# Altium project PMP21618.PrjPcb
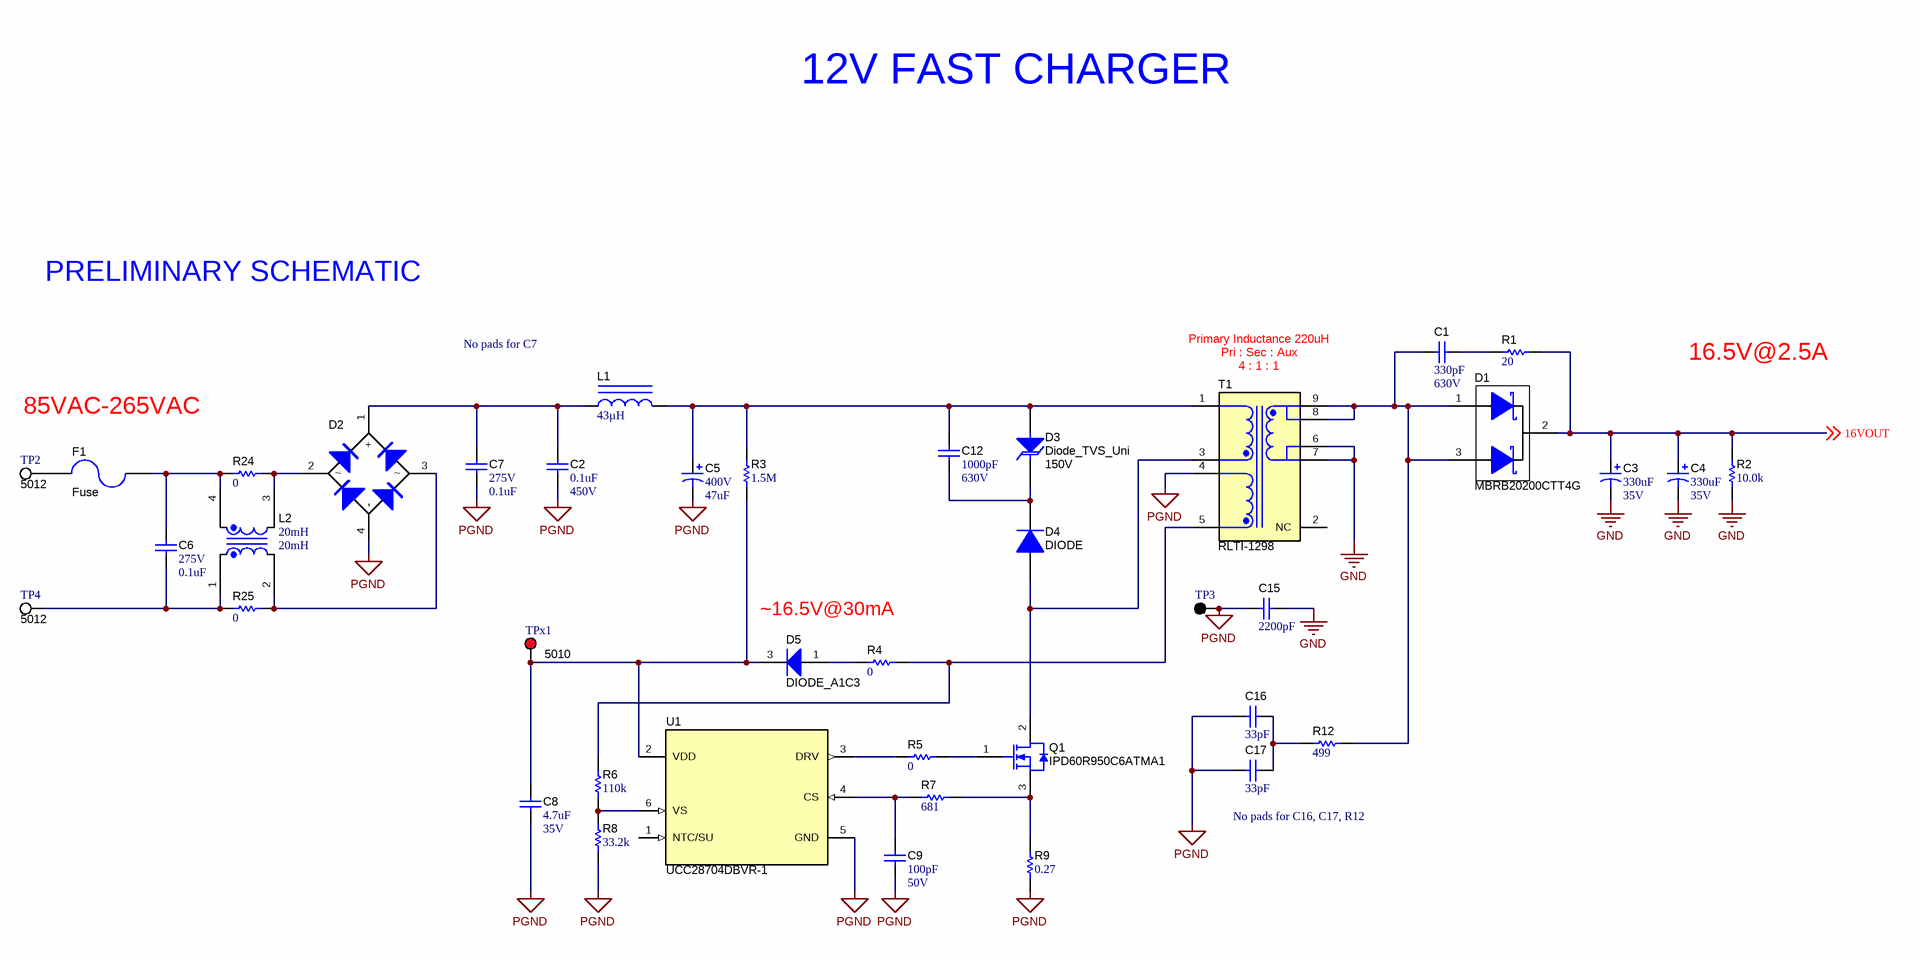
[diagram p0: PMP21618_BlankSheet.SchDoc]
TID: N/A; TechSupport: http://www.ti.com/support; SCH_Rev: A; PRJ_Number: PMP21618; PRJ_Engineer: S. Abedin; PRJ_Customer: Public Release; PCB_Rev: A; PCB_Layout: S. Abedin; CopyrightYear: 2017
2 sheets, 79 parts. Net scope: global (net labels, ports and power ports of the same name join across sheets).
Board file: PMP21618_PCB.PcbDoc
Sheets:
  PMP21618_BlankSheet.SchDoc
  BQ24725Z.SchDoc

## Sheet PMP21618_BlankSheet.SchDoc
size 431 x 279 mm; Date: Not shown in title block; ApprovedBy: Not shown in title block; CheckedBy: Not shown in title block; Author: Not shown in title block; CompanyName: Not shown in title block; Engineer: Not shown in title block; Organization: Not shown in title block; Address1: Not shown in title block; Address2: Not shown in title block; Address3: Not shown in title block; Address4: Not shown in title block; DocumentNumber: 1; Revision: Use project parameter SCH_Rev; SheetNumber: 1; SheetTotal: 2; PageSetup: Record=PageOptions¦CenterHorizontal=True¦CenterVertical=True¦PrintScale=1.00¦XCorrection=1.00¦YCorrection=1.00¦PrintKind=0¦BorderSize=5000000¦LeftOffset=0¦BottomOffset=0¦Orientation=2¦PaperLength=1000¦PaperWidth=1000¦Scale=100¦PaperSource=15¦PrintQuality=600¦MediaType=1¦DitherType=10¦PaperKind=Letter¦PrintScaleMode=1

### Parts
C1  ValueDisplayed: 330pF  VDC_V: 630V  [1206]  (hidden comment: Capacitor)
C2  ValueDisplayed: 0.1uF  VDC_V: 450V  [1206_190]  (hidden comment: Capacitor)
C3  ValueDisplayed: 330uF  VDC_V: 35V  [Chemi-Con_1000x1600]  (hidden comment: Cap_Polarized)
C4  ValueDisplayed: 330uF  VDC_V: 35V  [Chemi-Con_1000x1600]  (hidden comment: Cap_Polarized)
C5  VDC_V: 400V  ValueDisplayed: 47uF  [EE_1800x2000_HorizontalUp]  (hidden comment: EEU-EE2G470S)
C6  VDC_V: 275V  ValueDisplayed: 0.1uF  [WCAP-FTX2_1800x600x1200]  (hidden comment: 890324025017)
C7  VDC_V: 275V  ValueDisplayed: 0.1uF  [WCAP-FTX2_1800x600x1200]  (hidden comment: 890324025017)
C8  ValueDisplayed: 4.7uF  VDC_V: 35V  [0805_HV]  (hidden comment: Capacitor)
C9  ValueDisplayed: 100pF  VDC_V: 50V  [0402S]  (hidden comment: Capacitor)
C12  ValueDisplayed: 1000pF  VDC_V: 630V  [1206]  (hidden comment: Capacitor)
C15  ValueDisplayed: 2200pF  [KY_800x500x1100]  (hidden comment: DE2E3KY222MA2BM01F)
C16  ValueDisplayed: 33pF  [KY_800x500x1100_7_5]  (hidden comment: DE21XKY330JN3AM02F)
C17  ValueDisplayed: 33pF  [KY_800x500x1100_7_5]  (hidden comment: DE21XKY330JN3AM02F)
D1  MBRB20200CTT4G  [DDPAK]
D2  DIODE_BRIDGE_Pos1_Neg4_AC23  [Z4-D]  (value not drawn)
D3  Diode_TVS_Uni  value 150V  [SMC]
D4  DIODE  [SMA]
D5  DIODE_A1C3  [SOT-23]
F1  Fuse  [FUSE_372]
L1  ValueDisplayed: 43µH  [WE-FI_1300x650]  (hidden comment: 7447034)
L2  value 20mH  ValueDisplayed: 20mH  [IND_WE-CMB-S]  (hidden comment: 744822120)
Q1  IPD60R950C6ATMA1  [DPAK]
R1  ValueDisplayed: 20  [1206]  (hidden comment: Resistor)
R2  ValueDisplayed: 10.0k  [0402S]  (hidden comment: Resistor)
R3  ValueDisplayed: 1.5M  [0805_HV]  (hidden comment: Resistor)
R4  ValueDisplayed: 0  [0603]  (hidden comment: Resistor)
R5  ValueDisplayed: 0  [0402S]  (hidden comment: Resistor)
R6  ValueDisplayed: 110k  [0402S]  (hidden comment: Resistor)
R7  ValueDisplayed: 681  [0402S]  (hidden comment: Resistor)
R8  ValueDisplayed: 33.2k  [0402S]  (hidden comment: Resistor)
R9  ValueDisplayed: 0.27  [1210L]  (hidden comment: Resistor)
R12  ValueDisplayed: 499  [0805_HV]  (hidden comment: RG2012P-4990-B-T5)
R24  ValueDisplayed: 0  [2010]  (hidden comment: Resistor)
R25  ValueDisplayed: 0  [2010]  (hidden comment: Resistor)
T1  RLTI-1298  [Renco_RLTI-1298]
TP2  5012  [Keystone5012]
TP3  5011  [Keystone5011]  (value not drawn)
TP4  5012  [Keystone5012]
TPx1  5010  [Keystone5010]
U1  UCC28704DBVR-1  [DBV0006A_N]

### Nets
GND: C3.2(-) C4.2(-) C15.1 R2.1 T1.6 T1.7
PGND: C2.2 C5.2(-) C7.2 C8.2 C9.2 C15.2 C16.2 C17.2 D2.4(-) R8.1 R9.1 T1.4 TP3.1 U1.5(GND)
16VOUT: C3.1(+) C4.1(+) D1.2(K) R1.2 R2.2 ; off-sheet 16VOUT
NetC1_1: C1.1 R1.1
NetC1_2: C1.2 D1.1(A) D1.3(A) R12.2 T1.8 T1.9
NetC2_1: C2.1 C7.1 D2.1(+) L1.1
NetC5_1: C5.1(+) C12.1 D3.2(A) L1.2 R3.2 T1.1
NetC6_1: C6.1 F1.1 L2.4 R24.1
NetC6_2: C6.2 L2.1 R25.1 TP4.1
NetC8_1: C8.1 D5.3(K) R3.1 TPx1.1 U1.2(VDD)
NetC9_1: C9.1 R7.1 U1.4(CS)
NetC12_2: C12.2 D3.1(K) D4.1(K)
NetC16_1: C16.1 C17.1 R12.1
NetD2_2: D2.2 L2.3 R24.2
NetD2_3: D2.3 L2.2 R25.2
NetD4_2: D4.2(A) Q1.2(D) T1.3
NetD5_1: D5.1(A) R4.1
NetF1_2: F1.2 TP2.1
NetQ1_1: Q1.1(G) R5.2
NetQ1_3: Q1.3(S) R7.2 R9.2
NetR4_2: R4.2 R6.2 T1.5
NetR5_1: R5.1 U1.3(DRV)
NetR6_1: R6.1 R8.2 U1.6(VS)

Not connected (* = marked no-connect by the designer): T1 2(NC); U1 1(NTC/SU)

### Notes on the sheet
- 12V FAST CHARGER
- PRELIMINARY SCHEMATIC
- No pads for C7
- (near T1) Pri : Sec : Aux
- (near T1) 4 : 1 : 1
- Primary Inductance 220uH
- 16.5V@2.5A
- 85VAC-265VAC
- 6.5V@30mA
- (near C17) No pads for C16, C17, R12

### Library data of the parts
C1 = CMP-0008887-2: CAP, CERM, 330 pF, 630 V, +/- 5%, C0G/NP0, 1206; PartNumber: GRM31A5C2J331JW01D; Manufacturer: MuRata; Polarized: N; Value: 330pF; U/M: EA; Value1: Unknown; TaMin_C: -55°C; TaMax_C: 125°C; SizeArea_mm2: 5.12; SizeAreaWB_mm2: 10.92; SizeX_mm: 3.2; SizeY_mm: 1.6; SizeZ_mm: 1.35; AEC Category: Q200
C2 = CMP-0008727-2: CAP, CERM, 0.1 uF, 450 V, +/- 10%, X7T, 1206_190; PartNumber: C3216X7T2W104K160AA; Manufacturer: TDK; Polarized: N; Value: 0.1uF; U/M: EA; Cap_F: 100nF; Value1: Unknown; TaMin_C: -55°C; TaMax_C: 125°C; Cap_Case: 1206; SizeArea_mm2: 5.12; SizeAreaWB_mm2: 10.92; SizeX_mm: 3.2; SizeY_mm: 1.6; SizeZ_mm: 1.9; AEC Category: Q200
C3 C4 = CMP-0010424-2: CAP, AL, 330 uF, 35 V, +/- 20%, TH; PartNumber: EKZE350ELL331MJ16S; Manufacturer: Chemi-Con; Polarized: Y; CompType: Capacitor; Value: 330uF; U/M: EA; Cap_F: 330µF; Value1: Unknown; IRMS_A: 1.43A; TaMin_C: -40°C; TaMax_C: 105°C; Cap_Case: 10x16; SizeAreaWB_mm2: 144; SizeArea_mm2: 100; SizeX_mm: 10; SizeZ_mm: 17.5; AEC Category: Q200; AEC Qualified: N
C5 = CMP-0010026-3: CAP, AL, 47 uF, 400 V, +/- 20%, TH; Manufacturer: Panasonic; TaMin_C: -25°C; Polarized: Y; SizeAreaWB_mm2: 400; Value1: Unknown; U/M: EA; Value: 47uF; TaMax_C: 105°C; SizeZ_mm: 22; SizeX_mm: 18; Cap_Case: 18x20; SizeArea_mm2: 324; CompType: Capacitor; AEC Qualified: N; Cap_F: 47µF; IRMS_A: 1.18A; AEC Category: Q200
C6 C7 = CMP-0012314-3: CAP, Film, 0.1 uF, 275 V, +/- 10%, TH; Manufacturer: Wurth Elektronik; TaMin_C: -40°C; Polarized: N; Value1: Unknown; Value: 0.1uF; TaMax_C: 105°C; Cap_Case: 18x6x12mm; Cap_F: 100nF; AEC Category: Q200
C8 = CMP-0007885-2: CAP, CERM, 4.7 uF, 35 V, +/- 10%, X7R, 0805; PartNumber: C2012X7R1V475K125AC; Manufacturer: TDK; Polarized: N; Value: 4.7uF; U/M: EA; Cap_F: 4.7µF; ESR_ohm: 2.346m; Value1: 0.002346 ohm; IRMS_A: 4.26021A; TaMin_C: -55°C; TaMax_C: 125°C; Cap_Case: 0805; SizeArea_mm2: 2.5; SizeAreaWB_mm2: 6.75; SizeX_mm: 2; SizeY_mm: 1.25; SizeZ_mm: 1.45; AEC Category: Q200
C9 = CMP-0006410-2: CAP, CERM, 100 pF, 50 V, +/- 5%, C0G/NP0, 0402; PartNumber: GRM1555C1H101JA01D; Manufacturer: MuRata; Polarized: N; Value: 100pF; U/M: EA; Value1: Unknown; TaMin_C: -55°C; TaMax_C: 125°C; Cap_Case: 0402; SizeArea_mm2: 0.5; SizeAreaWB_mm2: 3; SizeX_mm: 1; SizeZ_mm: 0.6; AEC Category: Q200
C12 = CMP-0008909-2: CAP, CERM, 1000 pF, 630 V, +/- 10%, X7R, 1206; PartNumber: GRM31BR72J102KW01L; Manufacturer: MuRata; Polarized: N; Value: 1000pF; U/M: EA; Cap_F: 1nF; Value1: Unknown; TaMin_C: -55°C; TaMax_C: 125°C; SizeArea_mm2: 5.12; SizeAreaWB_mm2: 10.92; SizeX_mm: 3.2; SizeY_mm: 1.6; SizeZ_mm: 1.35; AEC Category: Q200
C15 = CMP-0067532-1: CAP, CERM, 2200 pF, X1 250 VAC/Y2 250 VAC, +/- 20%, E, 8x5mm; Manufacturer: MuRata; TaMin_C: -40°C; AC_Safety: X1Y2; Polarized: N; SizeAreaWB_mm2: 70.0; Value1: Unknown; U/M: EA; Value: 2200pF; TaMax_C: 125°C; VAC_X: 250; SizeZ_mm: 11.0; SizeX_mm: 8.0; SizeY_mm: 5.0; Cap_Case: 8x5x11mm; Value2: V; SizeArea_mm2: 40.0; Cap_F: 2.2nF; AEC Category: Q200
C16 C17 = CMP-0081721-1: CAP, CERM, 33 pF, X1 250 VAC/Y2 250 VAC, +/- 5%, SL, 8x5mm; Manufacturer: MuRata; TaMin_C: -40°C; Polarized: N; AC_Safety: X1Y2; SizeAreaWB_mm2: 71.05; U/M: EA; Value: 33pF; TaMax_C: 125°C; VAC_Y: 250V; SizeZ_mm: 11; SizeX_mm: 8.15; SizeY_mm: 5; Cap_Case: 8x5x11mm; SizeArea_mm2: 40.75; AEC Category: Q200
D1 = CMP-0028500-3: Diode, Schottky, 200 V, 20 A, DDPAK; Manufacturer: ON Semiconductor; Io_A: 20A; Green_Lifecycle: Not Set; SizeAreaWB_mm2: 209.6992; Vr_V: 200V; Green_REACh: Incomplete; TJmax_C: 150°C; Value: 200V; SizeZ_mm: 4.445; SizeX_mm: 15.245; SizeY_mm: 10.16; Vf_V: 1V; SizeArea_mm2: 154.8892; AEC Category: Q101; RJC_CperW: 2
D2 = CMP-0029244-3: Diode, P-N-Bridge, 600 V, 4 A, Z4-D; PartNumber: Z4DGP406L-HF; Manufacturer: Comchip Technology; Vf_V: 9.5dV; Value: 600V; Value1: 4A; Value2: 0.95V; TJmax_C: 175°C; AEC Category: Q101; AEC Qualified: N; Green_Lifecycle: Not Set; Green_REACh: Incomplete; SizeArea_mm2: 85.05; SizeAreaWB_mm2: 126.25; SizeX_mm: 10.5; SizeY_mm: 8.1; SizeZ_mm: 1.55
D3 = CMP-0005708-2: Diode, TVS, Uni, 150 V, 243 Vc, SMC; PartNumber: SMCJ150A-TP; Manufacturer: Micro Commercial Components; U/M: EA; Value1: W; SizeAreaWB_mm2: 83.2686; SizeArea_mm2: 50.5686; SizeX_mm: 8.13; SizeY_mm: 6.22; SizeZ_mm: 2.6; AEC Category: Q101; AEC Qualified: N
D4 = CMP-0029033-2: Diode, Ultrafast, 600 V, 1 A, AEC-Q101, SMA; PartNumber: MURA160T3G; Manufacturer: ON Semiconductor; Vf_V: 1.05V; Value: 600V; Value1: 1A; TJmax_C: 175°C; SizeAreaWB_mm2: 37.3428; SizeArea_mm2: 16.3228; SizeX_mm: 5.59; SizeY_mm: 2.92; SizeZ_mm: 2.87; AEC Category: Q101; AEC Qualified: Y; Green_Lifecycle: Active; Green_REACh: Passed
D5 = CMP-0076901-2: Diode, Switching, 200 V, 0.2 A, SOT-23; PartNumber: BAS21-7-F; Manufacturer: Diodes Inc.; Vf_V: 1.25V; Value: 200V; Value1: 0.2A; Io_A: 2dA; TJmax_C: 150°C; SizeAreaWB_mm2: 14.0; SizeArea_mm2: 7.5; SizeX_mm: 2.5; SizeY_mm: 3.0; SizeZ_mm: 1.1; AEC Category: Q101; Green_Lifecycle: Active; Green_REACh: Passed
F1 = CMP-0003553-2: Fuse, 1.25 A, 250VAC/VDC, TH; PartNumber: 37211250001; Manufacturer: Littelfuse; VDC_V: 250V; Irating_A: 1.25A
L1 = CMP-0750103-1: Inductor, Toroid, Ferrite, 43 µH, 1 A, 0.06 ohm, TH; Manufacturer: Wurth Elektronik; Irms: 2.6A @ 40C rise; SizeArea_mm2: 84.5; SizeZ_mm: 13; SizeX_mm: 6.5; DCR_ohm: 0.06; AEC Qualified: N; Imax_A: 1A; SizeAreaWB_mm2: 127.5; AEC Category: Q200; Value: 43uH
L2 = CMP-0084404-1: Coupled inductor, 20 mH, 0.54 ohm, TH; Manufacturer: Wurth Elektronik; AEC Category: Q200; DCR_ohm: 5.4d; AEC Qualified: N
Q1 = CMP-0067579-2: MOSFET, N-CH, 600 V, 4.4 A, DPAK; Alternate Manufacturer: None; Manufacturer: Infineon Technologies; QgTyp_nC: 13.0; SizeAreaWB_mm2: 101.7114; Vgs_V: 20V; Value1: ? ohm; VdsMax_V: 600V; Value: 600V; IdsMax_A: 4.4A; SizeZ_mm: 2.29; SizeX_mm: 9.91; SizeY_mm: 6.54; Value2: 13 nC; SizeArea_mm2: 64.8114; ChType: N; AEC Category: Q101; ChMode: Enhancement
R1 = CMP-0018627-3: RES, 20, 5%, 0.25 W, AEC-Q200 Grade 0, 1206; PartNumber: CRCW120620R0JNEA; Manufacturer: Vishay-Dale; Value: 20; Value_Code: 20R0; Power_W: 250mW; Value2: 0.25W; VDC_V: 200V; TempCo: 200 ppm/C; SizeArea_mm2: 5.12; SizeX_mm: 3.2; SizeY_mm: 1.6; SizeZ_mm: 1.35; EIA_Code: E24; AEC Category: Q200; AEC Qualified: Y; AEC Grade: 0
R2 = CMP-0025958-3: RES, 10.0 k, 1%, 0.063 W, AEC-Q200 Grade 0, 0402; PartNumber: CRCW040210K0FKED; Manufacturer: Vishay-Dale; Value: 10.0k; Res_ohm: 10k; Value_Code: 10k0; Power_W: 63mW; Value2: 0.063W; VDC_V: 50V; TempCo: 100 ppm/C; SizeArea_mm2: 0.5; SizeX_mm: 1; SizeZ_mm: 0.6; EIA_Code: E96; AEC Category: Q200; AEC Qualified: Y; AEC Grade: 0
R3 = CMP-0020484-3: RES, 1.5 M, 5%, 0.125 W, AEC-Q200 Grade 0, 0805; PartNumber: CRCW08051M50JNEA; Manufacturer: Vishay-Dale; Value: 1.5Meg; Value_Code: 1M50; Power_W: 125mW; Value2: 0.125W; VDC_V: 150V; TempCo: 200 ppm/C; SizeArea_mm2: 2.5; SizeX_mm: 2; SizeY_mm: 1.25; SizeZ_mm: 1.45; EIA_Code: E24; AEC Category: Q200; AEC Qualified: Y; AEC Grade: 0
R4 = CMP-0025697-4: RES, 0, 5%, 0.1 W, AEC-Q200 Grade 0, 0603; PartNumber: CRCW06030000Z0EA; Manufacturer: Vishay-Dale; Value: 0; Value_Code: 0000; Power_W: 100mW; Value2: 0.1W; VDC_V: 75V; TempCo: 200 ppm/C; SizeArea_mm2: 1.28; SizeX_mm: 1.6; SizeY_mm: 0.8; SizeZ_mm: 1; EIA_Code: E24; AEC Category: Q200; AEC Qualified: Y
R5 = CMP-0026822-3: RES, 0, 5%, 0.063 W, AEC-Q200 Grade 0, 0402; PartNumber: CRCW04020000Z0ED; Manufacturer: Vishay-Dale; Value: 0; Value_Code: 0000; Power_W: 63mW; Value2: 0.063W; VDC_V: 50V; TempCo: 200 ppm/C; SizeArea_mm2: 0.5; SizeX_mm: 1; SizeZ_mm: 0.6; EIA_Code: E24; AEC Category: Q200; AEC Qualified: Y
R6 = CMP-0026828-2: RES, 110 k, 5%, 0.063 W, AEC-Q200 Grade 0, 0402; PartNumber: CRCW0402110KJNED; Manufacturer: Vishay-Dale; Value: 110k; Power_W: 63mW; Value2: 0.063W; VDC_V: 50V; TempCo: 200 ppm/C; SizeArea_mm2: 0.5; SizeX_mm: 1; SizeZ_mm: 0.6; EIA_Code: E24; AEC Category: Q200; AEC Qualified: Y; AEC Grade: 0
R7 = CMP-0026505-2: RES, 681, 1%, 0.063 W, AEC-Q200 Grade 0, 0402; PartNumber: CRCW0402681RFKED; Manufacturer: Vishay-Dale; Value: 681; Value_Code: 681R; Power_W: 63mW; Value2: 0.063W; VDC_V: 50V; TempCo: 100 ppm/C; SizeArea_mm2: 0.5; SizeX_mm: 1; SizeZ_mm: 0.6; EIA_Code: E96; AEC Category: Q200; AEC Qualified: Y; AEC Grade: 0
R8 = CMP-0026298-2: RES, 33.2 k, 1%, 0.063 W, AEC-Q200 Grade 0, 0402; PartNumber: CRCW040233K2FKED; Manufacturer: Vishay-Dale; Value: 33.2k; Value_Code: 33k2; Power_W: 63mW; Value2: 0.063W; VDC_V: 50V; TempCo: 100 ppm/C; SizeArea_mm2: 0.5; SizeX_mm: 1; SizeZ_mm: 0.6; EIA_Code: E96; AEC Category: Q200; AEC Qualified: Y; AEC Grade: 0
R9 = CMP-0015177-2: RES, 0.27, 1%, 0.5 W, 1210; PartNumber: MCR25JZHFLR270; Manufacturer: Rohm; Value: 0.27; Res_ohm: 2.7d; Value_Code: R270; Power_W: 500mW; Value2: 0.5W; VDC_V: 0V; TempCo: 200 ppm/C; SizeArea_mm2: 8; SizeAreaWB_mm2: 14.7; SizeX_mm: 3.2; SizeY_mm: 2.5; SizeZ_mm: 1.35; EIA_Code: E96; U/M: EA; AEC Category: Q200
R12 = CMP-0019000-2: RES, 499, 0.1%, 0.125 W, 0805; Manufacturer: Susumu Co Ltd; Power_W: 125mW; TempCo: 25 ppm/C; Value_Code: 499R; U/M: EA; Value: 499; EIA_Code: E192; SizeX_mm: 2; SizeY_mm: 1.25; SizeZ_mm: 1.45; Value2: 0.125W; SizeArea_mm2: 2.5; VDC_V: 100V; AEC Category: Q200
R24 R25 = CMP-0016044-3: RES, 0, 5%, 0.75 W, AEC-Q200 Grade 0, 2010; PartNumber: CRCW20100000Z0EF; Manufacturer: Vishay-Dale; Value: 0; Value_Code: 0000; Power_W: 750mW; Value2: 0.75W; TempCo: ppm/C; SizeArea_mm2: 12.5; SizeX_mm: 5; SizeY_mm: 2.5; SizeZ_mm: 1.66; EIA_Code: E24; AEC Category: Q200; AEC Qualified: Y
T1 = CMP-0084219-2: Transformer, 220 uH, TH; Manufacturer: Renco Electronics; SizeAreaWB_mm2: 1219.9488; SizeArea_mm2: 1083.8688; AEC Qualified: N; Ns2toNp: 0.25; Lp: 220; AEC Category: Q200; Value: 220uH; SizeZ_mm: 19.05; Ind_H: 220µH; SizeY_mm: 30.48; LeakageInd_H: 7µH; Rsec2_ohm: 0.012; Rsec1_ohm: 0.04; DCR_ohm: 0.1; SizeX_mm: 35.56
TP2 TP4 = CMP-0055149-1: Test Point, Multipurpose, White, TH; Manufacturer: Keystone; ContactFinish: Silver; Green_Lifecycle: Active; Green_REACh: Passed; CNHeader: FALSE; CT: TRUE
TP3 = CMP-0055148-1: Test Point, Multipurpose, Black, TH; Manufacturer: Keystone; ContactFinish: Silver; Green_Lifecycle: Active; Green_REACh: Passed; CNHeader: FALSE; CT: TRUE
TPx1 = CMP-0055147-1: Test Point, Multipurpose, Red, TH; Manufacturer: Keystone; ContactFinish: Silver; Green_Lifecycle: Active; Green_REACh: Passed; CNHeader: FALSE; CT: TRUE
U1 = CMP-0074087-1: Off-Line Constant-Voltage Constant-Current Flyback Controller With Primary-Side Regulation (PSR), DBV0006A (SOT-23-6); Alternate PartNumber: UCC28704DBVT-1; Alternate Manufacturer: Texas Instruments; Green_Lifecycle: Active; SizeAreaWB_mm2: 14.82; Green_REACh: Passed; U/M: EA; SizeZ_mm: 1.45; SizeX_mm: 2.8; SizeY_mm: 2.9; SizeArea_mm2: 8.12; CompType: IC

## Sheet BQ24725Z.SchDoc
size 431 x 279 mm; Date: Not shown in title block; ApprovedBy: Not shown in title block; CheckedBy: Not shown in title block; Author: Not shown in title block; CompanyName: Not shown in title block; Engineer: Not shown in title block; Organization: Not shown in title block; Address1: Not shown in title block; Address2: Not shown in title block; Address3: Not shown in title block; Address4: Not shown in title block; DocumentNumber: 2; Revision: Use project parameter SCH_Rev; SheetNumber: 2; SheetTotal: 2; PageSetup: Record=PageOptions¦CenterHorizontal=True¦CenterVertical=True¦PrintScale=1.00¦XCorrection=1.00¦YCorrection=1.00¦PrintKind=0¦BorderSize=5000000¦LeftOffset=0¦BottomOffset=0¦Orientation=2¦PaperLength=1000¦PaperWidth=1000¦Scale=100¦PaperSource=15¦PrintQuality=600¦MediaType=1¦DitherType=10¦PaperKind=Letter¦PrintScaleMode=1
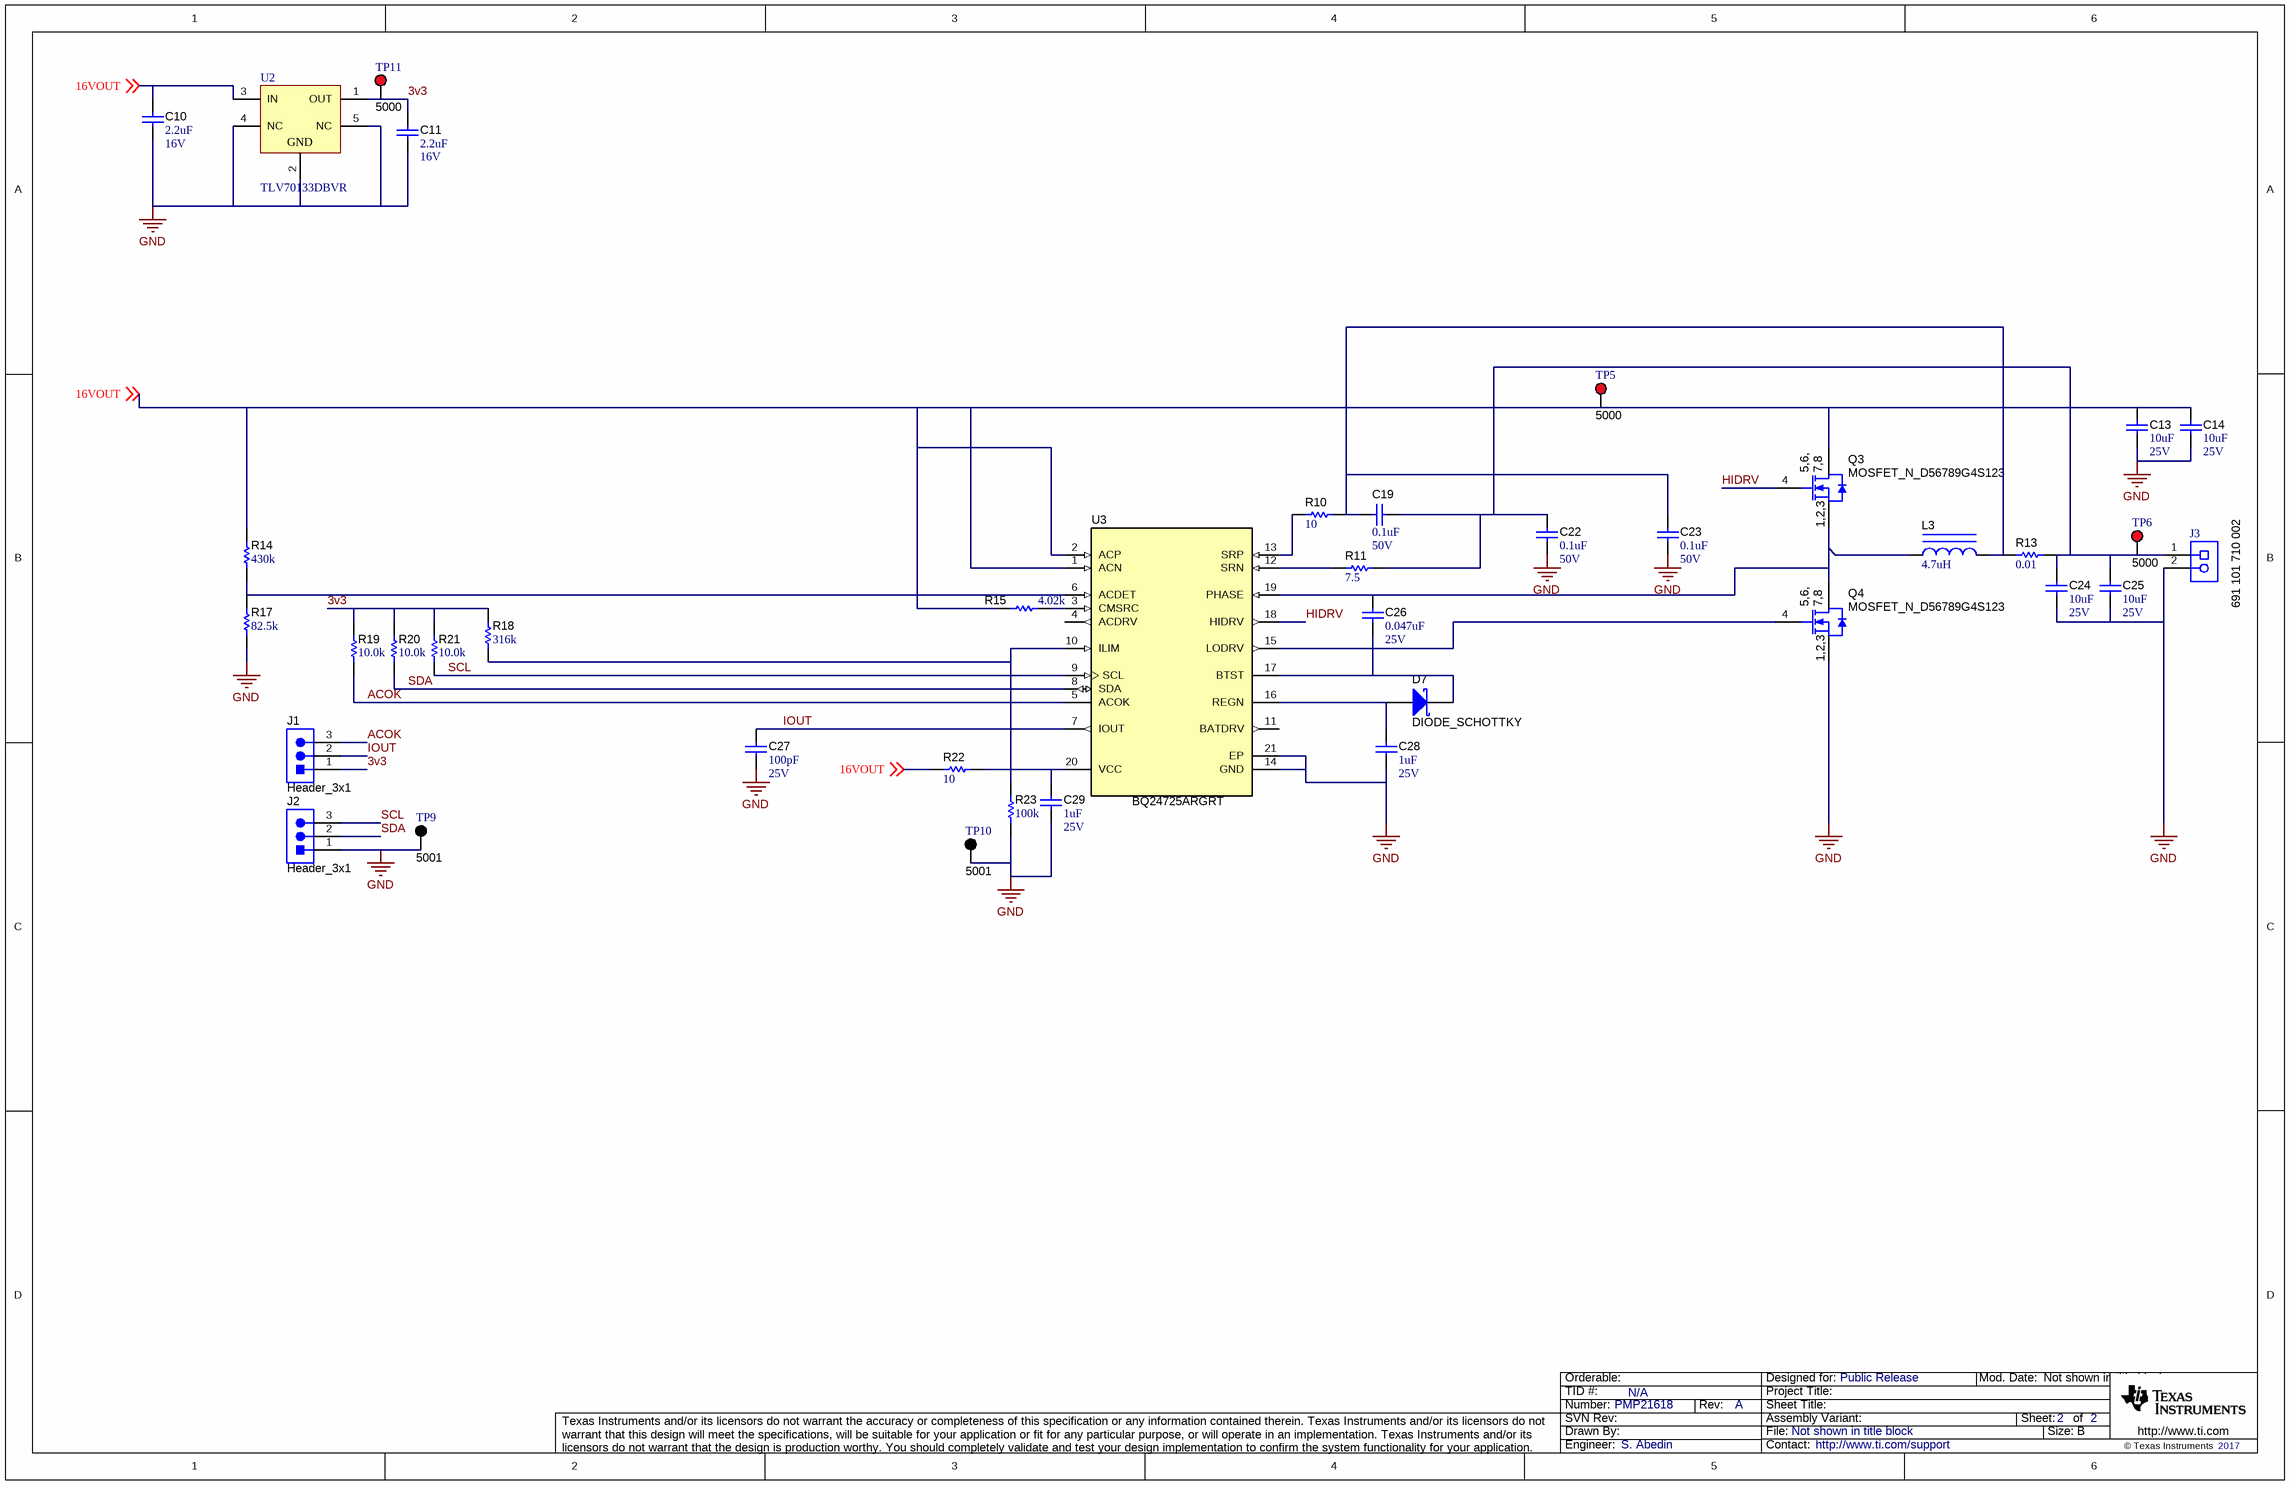
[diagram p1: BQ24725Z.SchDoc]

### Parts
C10  ValueDisplayed: 2.2uF  VDC_V: 16V  [0402S]  (hidden comment: Capacitor)
C11  ValueDisplayed: 2.2uF  VDC_V: 16V  [0402S]  (hidden comment: Capacitor)
C13  ValueDisplayed: 10uF  VDC_V: 25V  [0805_HV]  (hidden comment: Capacitor)
C14  ValueDisplayed: 10uF  VDC_V: 25V  [0805_HV]  (hidden comment: Capacitor)
C19  ValueDisplayed: 0.1uF  VDC_V: 50V  [0402S]  (hidden comment: Capacitor)
C22  ValueDisplayed: 0.1uF  VDC_V: 50V  [0402S]  (hidden comment: Capacitor)
C23  ValueDisplayed: 0.1uF  VDC_V: 50V  [0402S]  (hidden comment: Capacitor)
C24  ValueDisplayed: 10uF  VDC_V: 25V  [0805_HV]  (hidden comment: Capacitor)
C25  ValueDisplayed: 10uF  VDC_V: 25V  [0805_HV]  (hidden comment: Capacitor)
C26  ValueDisplayed: 0.047uF  VDC_V: 25V  [0402S]  (hidden comment: Capacitor)
C27  ValueDisplayed: 100pF  VDC_V: 25V  [0402S]  (hidden comment: Capacitor)
C28  ValueDisplayed: 1uF  VDC_V: 25V  [0402S]  (hidden comment: Capacitor)
C29  ValueDisplayed: 1uF  VDC_V: 25V  [0402S]  (hidden comment: Capacitor)
D7  DIODE_SCHOTTKY  [SOD-323]
J1  Header_3x1  [Mill-Max_800-10-003-10-001000]
J2  Header_3x1  [Mill-Max_800-10-003-10-001000]
J3  691 101 710 002  [Wurth_691101710002]
L3  ValueDisplayed: 4.7uH  [XAL4030]  (hidden comment: Inductor_Iron)
Q3  MOSFET_N_D56789G4S123  [DNH0008A]
Q4  MOSFET_N_D56789G4S123  [DNH0008A]
R10  ValueDisplayed: 10  [0402S]  (hidden comment: Resistor)
R11  ValueDisplayed: 7.5  [0402S]  (hidden comment: Resistor)
R13  ValueDisplayed: 0.01  [1206]  (hidden comment: Resistor)
R14  ValueDisplayed: 430k  [0402S]  (hidden comment: Resistor)
R15  ValueDisplayed: 4.02k  [0402S]  (hidden comment: Resistor)
R17  ValueDisplayed: 82.5k  [0402S]  (hidden comment: Resistor)
R18  ValueDisplayed: 316k  [0402S]  (hidden comment: Resistor)
R19  ValueDisplayed: 10.0k  [0402S]  (hidden comment: Resistor)
R20  ValueDisplayed: 10.0k  [0402S]  (hidden comment: Resistor)
R21  ValueDisplayed: 10.0k  [0402S]  (hidden comment: Resistor)
R22  ValueDisplayed: 10  [0402S]  (hidden comment: Resistor)
R23  ValueDisplayed: 100k  [0402S]  (hidden comment: Resistor)
TP5  5000  [Keystone5000]
TP6  5000  [Keystone5000]
TP9  5001  [Keystone5001]
TP10  5001  [Keystone5001]
TP11  5000  [Keystone5000]
U2  PartNumber: TLV70133DBVR  [DBV0005A_N]  (hidden comment: TI-TLV7013XDBV5)
U3  BQ24725ARGRT  [RGR0020A]

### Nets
GND: C10.2 C11.2 C13.1 C14.1 C22.1 C23.1 C24.1 C25.1 C27.2 C28.2 C29.2 J2.1 J3.2 Q4.1(S) Q4.2(S) Q4.3(S) R17.1 R23.1 TP9.1 TP10.1 U2.2(GND) U2.4(NC) U2.5(NC) U3.14(GND) U3.21(EP)
3v3: C11.1 J1.1 R18.2 R19.1 R20.1 R21.1 TP11.1 U2.1(OUT)
16VOUT: C10.1 C13.2 C14.2 Q3.5(D) Q3.6(D) Q3.7(D) Q3.8(D) Q3.9(D) R14.2 R15.2 R22.1 TP5.1 U2.3(IN) U3.1(ACN) U3.2(ACP) ; off-sheet 16VOUT
ACOK: J1.3 R19.2 U3.5(ACOK)
HIDRV: Q3.4(G) U3.18(HIDRV)
IOUT: C27.1 J1.2 U3.7(IOUT)
SCL: J2.3 R21.2 U3.9(SCL)
SDA: J2.2 R20.2 U3.8(SDA)
NetC19_1: C19.1 C22.2 C24.2 C25.2 J3.1 R11.2 R13.2 TP6.1
NetC19_2: C19.2 C23.2 L3.2 R10.2 R13.1
NetC26_1: C26.1 L3.1 Q3.1(S) Q3.2(S) Q3.3(S) Q4.5(D) Q4.6(D) Q4.7(D) Q4.8(D) Q4.9(D) U3.19(PHASE)
NetC26_2: C26.2 D7.1(K) U3.17(BTST)
NetC28_1: C28.1 D7.2(A) U3.16(REGN)
NetC29_1: C29.1 R22.2 U3.20(VCC)
NetQ4_4: Q4.4(G) U3.15(LODRV)
NetR10_1: R10.1 U3.13(SRP)
NetR11_1: R11.1 U3.12(SRN)
NetR14_1: R14.1 R17.2 U3.6(ACDET)
NetR15_1: R15.1 U3.3(CMSRC)
NetR18_1: R18.1 R23.2 U3.10(ILIM)

Not connected (* = marked no-connect by the designer): U3 4(ACDRV) 11(BATDRV)

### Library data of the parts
C10 C11 = CMP-0006594-2: CAP, CERM, 2.2 uF, 16 V, +/- 10%, X5R, 0402; PartNumber: GRM155R61C225KE11D; Manufacturer: MuRata; Polarized: N; Value: 2.2uF; U/M: EA; Cap_F: 2.2µF; Value1: Unknown; TaMin_C: -55°C; TaMax_C: 85°C; Cap_Case: 0402; SizeArea_mm2: 0.5; SizeAreaWB_mm2: 3; SizeX_mm: 1; SizeZ_mm: 0.6; AEC Category: Q200
C13 C14 C24 C25 = CMP-0008414-2: CAP, CERM, 10 uF, 25 V, +/- 10%, X5R, 0805; PartNumber: TMK212BBJ106KG-T; Manufacturer: Taiyo Yuden; Polarized: N; Value: 10uF; U/M: EA; Cap_F: 10µF; Value1: Unknown; TaMin_C: -55°C; TaMax_C: 85°C; Cap_Case: 0805; SizeArea_mm2: 2.5; SizeAreaWB_mm2: 6.75; SizeX_mm: 2; SizeY_mm: 1.25; SizeZ_mm: 1.45; AEC Category: Q200
C19 C22 C23 = CMP-0006289-2: CAP, CERM, 0.1 uF, 50 V, +/- 10%, X6S, 0402; PartNumber: C1005X6S1H104K050BB; Manufacturer: TDK; Polarized: N; Value: 0.1uF; U/M: EA; Cap_F: 100nF; ESR_ohm: 0.039064; Value1: 0.039064 ohm; IRMS_A: 8.14669dA; TaMin_C: -55°C; TaMax_C: 105°C; Cap_Case: 0402; SizeArea_mm2: 0.5; SizeAreaWB_mm2: 3; SizeX_mm: 1; SizeZ_mm: 0.6; AEC Category: Q200
C26 = CMP-0006669-2: CAP, CERM, 0.047 uF, 25 V, +/- 10%, X7R, 0402; PartNumber: GRM155R71E473KA88D; Manufacturer: MuRata; Polarized: N; U/M: EA; Cap_F: 47nF; Value1: Unknown; TaMin_C: -55°C; TaMax_C: 125°C; Cap_Case: 0402; SizeArea_mm2: 0.5; SizeAreaWB_mm2: 3; SizeX_mm: 1; SizeZ_mm: 0.6; AEC Category: Q200
C27 = CMP-0006233-2: CAP, CERM, 100 pF, 25 V, +/- 5%, C0G/NP0, 0402; PartNumber: C0402C101J3GACTU; Manufacturer: Kemet; Polarized: N; Value: 100pF; U/M: EA; Value1: Unknown; TaMin_C: -55°C; TaMax_C: 125°C; Cap_Case: 0402; SizeArea_mm2: 0.5; SizeAreaWB_mm2: 3; SizeX_mm: 1; SizeZ_mm: 0.6; AEC Category: Q200
C28 C29 = CMP-0006608-2: CAP, CERM, 1 uF, 25 V, +/- 10%, X5R, 0402; PartNumber: GRM155R61E105KA12D; Manufacturer: MuRata; Polarized: N; Value: 1uF; U/M: EA; Cap_F: 1µF; Value1: Unknown; TaMin_C: -55°C; TaMax_C: 85°C; Cap_Case: 0402; SizeArea_mm2: 0.5; SizeAreaWB_mm2: 3; SizeX_mm: 1; SizeZ_mm: 0.6; AEC Category: Q200
D7 = CMP-0028455-2: Diode, Schottky, 30 V, 0.2 A, SOD-323; PartNumber: BAT54HT1G; Manufacturer: ON Semiconductor; Vf_V: 3.5dV; Value: 30V; Value1: 0.2A; Value2: 0.35V; Io_A: 2dA; SizeAreaWB_mm2: 8.695; SizeArea_mm2: 3.645; SizeX_mm: 2.7; SizeY_mm: 1.35; SizeZ_mm: 1; AEC Category: Q101; Green_Lifecycle: Active; Green_REACh: Passed
J1 J2 = CMP-0055086-1: Header, 100mil, 3x1, TH; PartNumber: 800-10-003-10-001000; Manufacturer: Mill-Max; Green_Lifecycle: Active; Green_REACh: Passed; CNHeader: TRUE; CT: FALSE
J3 = CMP-0054828-1: Terminal Block, 5 mm, 2x1, Tin, TH; Manufacturer: Wurth Elektronik; CNHeader: FALSE; Green_Lifecycle: Active; Green_REACh: Passed; CT: TRUE
L3 = CMP-0060990-1: Inductor, Shielded, Composite, 4.7 uH, 4.5 A, 0.0401 ohm, SMD; PartNumber: XAL4030-472MEB; Manufacturer: Coilcraft; Value: 4.7uH; Ind_H: 4.7µH; Imax_A: 4.5A; Irms: 5.1A @ 40C rise; Isat: 4.5A @ 30% inductance drop; DCR_ohm: 0.0401; SizeAreaWB_mm2: 25; SizeArea_mm2: 16; SizeX_mm: 4; SizeZ_mm: 3.1; AEC Category: Q200; Green_Lifecycle: Not Set; Green_REACh: Incomplete
Q3 Q4 = CMP-0000591-2: MOSFET, N-CH, 30 V, 14 A, DNH0008A (VSONP-8); PartNumber: CSD17578Q3A; Manufacturer: Texas Instruments; Alternate Manufacturer: None; ChType: N; Value: 30V; Value1: 0.008; Rdson45_ohm: 8.2m; Value2: 7.9 nC; QgTyp_nC: 7.9; Vgs_V: 20V; IdsMax_A: 14A; SizeAreaWB_mm2: 18.49; SizeArea_mm2: 10.89; SizeX_mm: 3.3; SizeZ_mm: 0.9; AEC Category: Q101; ChMode: Enhancement
R10 R22 = CMP-0026827-3: RES, 10, 5%, 0.063 W, AEC-Q200 Grade 0, 0402; PartNumber: CRCW040210R0JNED; Manufacturer: Vishay-Dale; Value: 10; Value_Code: 10R0; Power_W: 63mW; Value2: 0.063W; VDC_V: 50V; TempCo: 200 ppm/C; SizeArea_mm2: 0.5; SizeX_mm: 1; SizeZ_mm: 0.6; EIA_Code: E24; AEC Category: Q200; AEC Qualified: Y; AEC Grade: 0
R11 = CMP-0026977-3: RES, 7.5, 5%, 0.063 W, AEC-Q200 Grade 0, 0402; PartNumber: CRCW04027R50JNED; Manufacturer: Vishay-Dale; Value: 7.5; Value_Code: 7R50; Power_W: 63mW; Value2: 0.063W; VDC_V: 50V; TempCo: 200 ppm/C; SizeArea_mm2: 0.5; SizeX_mm: 1; SizeZ_mm: 0.6; EIA_Code: E24; AEC Category: Q200; AEC Qualified: Y; AEC Grade: 0
R13 = CMP-0018570-2: RES, 0.01, 1%, 1 W, 1206; PartNumber: WSLP1206R0100FEA; Manufacturer: Vishay-Dale; Value: 0.01; Value_Code: R010; Power_W: 1W; TempCo: 75 ppm/C; SizeArea_mm2: 5.12; SizeX_mm: 3.2; SizeY_mm: 1.6; SizeZ_mm: 1.35; EIA_Code: E96; U/M: EA; AEC Category: Q200
R14 = CMP-0026929-2: RES, 430 k, 5%, 0.063 W, AEC-Q200 Grade 0, 0402; PartNumber: CRCW0402430KJNED; Manufacturer: Vishay-Dale; Value: 430k; Power_W: 63mW; Value2: 0.063W; VDC_V: 50V; TempCo: 200 ppm/C; SizeArea_mm2: 0.5; SizeX_mm: 1; SizeZ_mm: 0.6; EIA_Code: E24; AEC Category: Q200; AEC Qualified: Y; AEC Grade: 0
R15 = CMP-0026405-2: RES, 4.02 k, 1%, 0.063 W, AEC-Q200 Grade 0, 0402; PartNumber: CRCW04024K02FKED; Manufacturer: Vishay-Dale; Value: 4.02k; Value_Code: 4k02; Power_W: 63mW; Value2: 0.063W; VDC_V: 50V; TempCo: 100 ppm/C; SizeArea_mm2: 0.5; SizeX_mm: 1; SizeZ_mm: 0.6; EIA_Code: E96; AEC Category: Q200; AEC Qualified: Y; AEC Grade: 0
R17 = CMP-0026574-2: RES, 82.5 k, 1%, 0.063 W, AEC-Q200 Grade 0, 0402; PartNumber: CRCW040282K5FKED; Manufacturer: Vishay-Dale; Value: 82.5k; Value_Code: 82k5; Power_W: 63mW; Value2: 0.063W; VDC_V: 50V; TempCo: 100 ppm/C; SizeArea_mm2: 0.5; SizeX_mm: 1; SizeZ_mm: 0.6; EIA_Code: E96; AEC Category: Q200; AEC Qualified: Y; AEC Grade: 0
R18 = CMP-0026288-2: RES, 316 k, 1%, 0.063 W, AEC-Q200 Grade 0, 0402; PartNumber: CRCW0402316KFKED; Manufacturer: Vishay-Dale; Value: 316k; Power_W: 63mW; Value2: 0.063W; VDC_V: 50V; TempCo: 100 ppm/C; SizeArea_mm2: 0.5; SizeX_mm: 1; SizeZ_mm: 0.6; EIA_Code: E96; AEC Category: Q200; AEC Qualified: Y; AEC Grade: 0
R19-R21 = CMP-0026769-2: RES, 10.0 k, 0.5%, 0.063 W, AEC-Q200 Grade 0, 0402; PartNumber: CRCW040210K0DHEDP; Manufacturer: Vishay-Dale; Value: 10.0k; Res_ohm: 10k; Value_Code: 10k0; Power_W: 63mW; Value2: 0.063W; VDC_V: 50V; TempCo: 50 ppm/C; SizeArea_mm2: 0.5; SizeX_mm: 1; SizeZ_mm: 0.6; EIA_Code: E192; AEC Category: Q200; AEC Qualified: Y; AEC Grade: 0
R23 = CMP-0025950-3: RES, 100 k, 1%, 0.063 W, AEC-Q200 Grade 0, 0402; PartNumber: CRCW0402100KFKED; Manufacturer: Vishay-Dale; Value: 100k; Power_W: 63mW; Value2: 0.063W; VDC_V: 50V; TempCo: 100 ppm/C; SizeArea_mm2: 0.5; SizeX_mm: 1; SizeZ_mm: 0.6; EIA_Code: E96; AEC Category: Q200; AEC Qualified: Y; AEC Grade: 0
TP5 TP6 TP11 = CMP-0055137-1: Test Point, Miniature, Red, TH; Manufacturer: Keystone; ContactFinish: Silver; Green_Lifecycle: Active; Green_REACh: Passed; CNHeader: FALSE; CT: TRUE
TP9 TP10 = CMP-0055138-1: Test Point, Miniature, Black, TH; Manufacturer: Keystone; ContactFinish: Silver; Green_Lifecycle: Active; Green_REACh: Passed; CNHeader: FALSE; CT: TRUE
U2 = CMP-0035538-1: Single Output LDO, 150 mA, Fixed 3.3 V Output, 2.5 to 24 V Input, with Ultra-Low IQ, 5-pin SOT-23 (DBV), -40 to 85 degC, Green (RoHS & no Sb/Br); Manufacturer: Texas Instruments; Accuracy(%): 2; Fixed Output Options(V): 3.3; Iout(Max)(A): 0.15; Iq(Typ)(mA): 0.032; SubFamily: Single Channel LDO; Vdo(Typ)(mV): 400; Vin(Max)(V): 24; Vin(Min)(V): 2.5
U3 = CMP-0034195-2: 1-4 Cell Li+ Battery SMBus Charge Controller with N-Channel Power MOSFET Selector, RGR0020A (VQFN-20); Manufacturer: Texas Instruments; Alternate PartNumber: BQ24725ARGRR; SizeAreaWB_mm2: 20.25; SizeArea_mm2: 12.25; SizeX_mm: 3.5; SizeZ_mm: 1.0; AEC Category: Q200; AEC Qualified: N; CompType: IC

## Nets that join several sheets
GND: PMP21618_BlankSheet (6 pins), BQ24725Z (25 pins)
16VOUT: PMP21618_BlankSheet (5 pins), BQ24725Z (15 pins)

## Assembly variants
001: not fitted C1 C12 FID1 FID2 FID3 R24 R25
